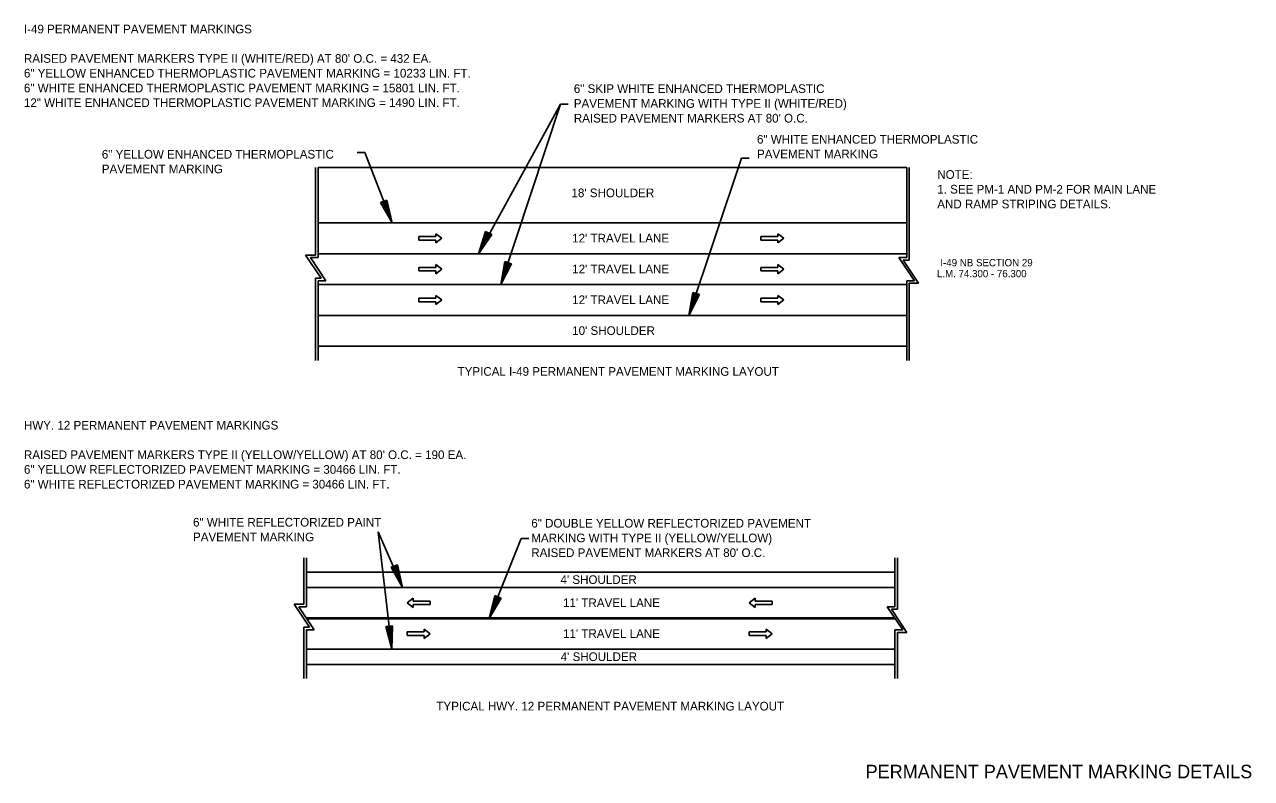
# Model space of a CAD drawing. Extents: x 2261938 to 2263136, y -3124572 to -3124216.
# Drawn here: x 2262297 to 2262456.3, y -3124313.5 to -3124215.6 of the extents above; entities that cross this region are included whole.
import ezdxf

# ---------------------------------------------------------------- set-up
doc = ezdxf.new("R2010")
doc.units = 0
for name, color, linetype in [('Default', 7, 'Continuous'), ('DSN_DRFT_Common-Annotations', 7, 'Continuous'), ('R_Draft', 7, 'Continuous'), ('SHET_Border-Text', 7, 'Continuous')]:
    doc.layers.add(name, color=color, linetype=linetype)

msp = doc.modelspace()

# ---------------------------------------------------------------- linework, layer by layer
at = {"layer": 'Default'}
for p, q in [((2262366.59, -3124225.98), (2262355.93, -3124245.39)), ((2262366.59, -3124225.98), (2262358.85, -3124249.39)), ((2262367.59, -3124225.98), (2262366.59, -3124225.98)), ((2262340.19, -3124232.23), (2262341.19, -3124232.23)), ((2262341.19, -3124232.23), (2262344.71, -3124241.39)), ((2262390.08, -3124233), (2262383.23, -3124253.39)), ((2262391.08, -3124233), (2262390.08, -3124233)), ((2262334.79, -3124234.19), (2262334.79, -3124245.56)), ((2262335.13, -3124234.19), (2262411.52, -3124234.19)), ((2262335.13, -3124234.19), (2262335.13, -3124245.89)), ((2262411.52, -3124234.19), (2262411.52, -3124245.89)), ((2262411.85, -3124234.19), (2262411.85, -3124246.23)), ((2262344.05, -3124238.43), (2262343.21, -3124238.75)), ((2262343.21, -3124238.75), (2262344.71, -3124241.39)), ((2262343.28, -3124238.73), (2262344.53, -3124240.93)), ((2262343.35, -3124238.7), (2262344.34, -3124240.44)), ((2262343.42, -3124238.67), (2262344.16, -3124239.98)), ((2262343.5, -3124238.64), (2262343.98, -3124239.5)), ((2262343.57, -3124238.62), (2262343.8, -3124239.03)), ((2262343.7, -3124238.57), (2262343.8, -3124239.03)), ((2262343.77, -3124238.54), (2262343.98, -3124239.5)), ((2262343.84, -3124238.51), (2262344.16, -3124239.98)), ((2262343.91, -3124238.49), (2262344.34, -3124240.44)), ((2262343.98, -3124238.46), (2262344.53, -3124240.93)), ((2262344.05, -3124238.43), (2262344.71, -3124241.39)), ((2262350.38, -3124242.79), (2262350.38, -3124243.17)), ((2262350.38, -3124242.79), (2262351.16, -3124243.39)), ((2262356.86, -3124242.51), (2262355.93, -3124245.39)), ((2262357.67, -3124242.91), (2262355.93, -3124245.39)), ((2262356.93, -3124242.54), (2262356.15, -3124244.94)), ((2262357.6, -3124242.87), (2262356.15, -3124244.94)), ((2262357, -3124242.57), (2262356.38, -3124244.48)), ((2262357.53, -3124242.84), (2262356.38, -3124244.48)), ((2262357.06, -3124242.61), (2262356.6, -3124244.03)), ((2262357.46, -3124242.81), (2262356.6, -3124244.03)), ((2262357.13, -3124242.64), (2262356.83, -3124243.58)), ((2262357.39, -3124242.77), (2262356.83, -3124243.58)), ((2262357.67, -3124242.91), (2262356.86, -3124242.51)), ((2262357.2, -3124242.67), (2262357.05, -3124243.13)), ((2262357.33, -3124242.74), (2262357.05, -3124243.13)), ((2262394.8, -3124242.79), (2262394.8, -3124243.17)), ((2262394.8, -3124242.79), (2262395.58, -3124243.39)), ((2262350.38, -3124243.17), (2262348.18, -3124243.17)), ((2262348.18, -3124243.17), (2262348.18, -3124243.62)), ((2262350.38, -3124243.62), (2262348.18, -3124243.62)), ((2262351.16, -3124243.39), (2262350.38, -3124243.99)), ((2262350.38, -3124243.62), (2262350.38, -3124243.99)), ((2262394.8, -3124243.17), (2262392.59, -3124243.17)), ((2262392.59, -3124243.17), (2262392.59, -3124243.62)), ((2262394.8, -3124243.62), (2262392.59, -3124243.62)), ((2262395.58, -3124243.39), (2262394.8, -3124243.99)), ((2262394.8, -3124243.62), (2262394.8, -3124243.99)), ((2262335.5, -3124248.56), (2262333.5, -3124245.56)), ((2262334.79, -3124245.56), (2262333.5, -3124245.56)), ((2262335.13, -3124245.89), (2262334.13, -3124245.89)), ((2262336.13, -3124248.89), (2262334.13, -3124245.89)), ((2262335.13, -3124245.39), (2262411.52, -3124245.39)), ((2262411.52, -3124245.89), (2262410.52, -3124245.89)), ((2262412.52, -3124248.89), (2262410.52, -3124245.89)), ((2262350.38, -3124247.17), (2262348.18, -3124247.17)), ((2262348.18, -3124247.17), (2262348.18, -3124247.62)), ((2262350.38, -3124247.62), (2262348.18, -3124247.62)), ((2262350.38, -3124246.79), (2262350.38, -3124247.17)), ((2262350.38, -3124246.79), (2262351.16, -3124247.39)), ((2262351.16, -3124247.39), (2262350.38, -3124247.99)), ((2262350.38, -3124247.62), (2262350.38, -3124247.99)), ((2262359.36, -3124246.4), (2262358.85, -3124249.39)), ((2262360.22, -3124246.69), (2262358.85, -3124249.39)), ((2262359.44, -3124246.43), (2262359.01, -3124248.92)), ((2262360.15, -3124246.66), (2262359.01, -3124248.92)), ((2262359.51, -3124246.45), (2262359.17, -3124248.43)), ((2262360.08, -3124246.64), (2262359.17, -3124248.43)), ((2262359.58, -3124246.47), (2262359.33, -3124247.95)), ((2262360, -3124246.61), (2262359.33, -3124247.95)), ((2262360.22, -3124246.69), (2262359.36, -3124246.4)), ((2262359.65, -3124246.5), (2262359.49, -3124247.47)), ((2262359.93, -3124246.59), (2262359.49, -3124247.47)), ((2262359.73, -3124246.52), (2262359.64, -3124246.99)), ((2262359.86, -3124246.57), (2262359.64, -3124246.99)), ((2262394.8, -3124247.17), (2262392.59, -3124247.17)), ((2262392.59, -3124247.17), (2262392.59, -3124247.62)), ((2262394.8, -3124247.62), (2262392.59, -3124247.62)), ((2262394.8, -3124246.79), (2262394.8, -3124247.17)), ((2262394.8, -3124246.79), (2262395.58, -3124247.39)), ((2262395.58, -3124247.39), (2262394.8, -3124247.99)), ((2262394.8, -3124247.62), (2262394.8, -3124247.99)), ((2262413.07, -3124249.23), (2262411.07, -3124246.23)), ((2262411.85, -3124246.23), (2262411.07, -3124246.23)), ((2262334.79, -3124248.56), (2262335.5, -3124248.56)), ((2262334.79, -3124259.23), (2262334.79, -3124248.56)), ((2262335.13, -3124259.23), (2262335.13, -3124248.89)), ((2262335.13, -3124248.89), (2262336.13, -3124248.89)), ((2262411.52, -3124259.23), (2262411.52, -3124248.89)), ((2262411.52, -3124248.89), (2262412.52, -3124248.89)), ((2262411.85, -3124259.23), (2262411.85, -3124249.23)), ((2262411.85, -3124249.23), (2262413.07, -3124249.23)), ((2262335.13, -3124249.39), (2262411.52, -3124249.39)), ((2262350.38, -3124250.79), (2262350.38, -3124251.17)), ((2262350.38, -3124250.79), (2262351.16, -3124251.39)), ((2262383.76, -3124250.41), (2262383.23, -3124253.39)), ((2262384.61, -3124250.69), (2262383.23, -3124253.39)), ((2262383.83, -3124250.43), (2262383.39, -3124252.92)), ((2262384.54, -3124250.67), (2262383.39, -3124252.92)), ((2262383.9, -3124250.45), (2262383.55, -3124252.43)), ((2262384.47, -3124250.64), (2262383.55, -3124252.43)), ((2262383.97, -3124250.48), (2262383.71, -3124251.96)), ((2262384.4, -3124250.62), (2262383.71, -3124251.96)), ((2262384.61, -3124250.69), (2262383.76, -3124250.41)), ((2262384.05, -3124250.5), (2262383.88, -3124251.47)), ((2262384.32, -3124250.6), (2262383.88, -3124251.47)), ((2262384.12, -3124250.53), (2262384.04, -3124251)), ((2262384.25, -3124250.57), (2262384.04, -3124251)), ((2262394.8, -3124250.79), (2262394.8, -3124251.17)), ((2262394.8, -3124250.79), (2262395.58, -3124251.39)), ((2262350.38, -3124251.17), (2262348.18, -3124251.17)), ((2262348.18, -3124251.17), (2262348.18, -3124251.62)), ((2262350.38, -3124251.62), (2262348.18, -3124251.62)), ((2262351.16, -3124251.39), (2262350.38, -3124251.99)), ((2262350.38, -3124251.62), (2262350.38, -3124251.99)), ((2262394.8, -3124251.17), (2262392.59, -3124251.17)), ((2262392.59, -3124251.17), (2262392.59, -3124251.62)), ((2262394.8, -3124251.62), (2262392.59, -3124251.62)), ((2262395.58, -3124251.39), (2262394.8, -3124251.99)), ((2262394.8, -3124251.62), (2262394.8, -3124251.99)), ((2262335.13, -3124253.39), (2262411.52, -3124253.39)), ((2262335.13, -3124257.39), (2262411.52, -3124257.39)), ((2262342.92, -3124281.48), (2262346.09, -3124288.71)), ((2262342.92, -3124281.48), (2262344.69, -3124296.71)), ((2262361.49, -3124282.35), (2262357.34, -3124292.71)), ((2262362.49, -3124282.35), (2262361.49, -3124282.35)), ((2262333.28, -3124284.87), (2262333.28, -3124290.87)), ((2262333.61, -3124284.87), (2262333.61, -3124291.21)), ((2262345.44, -3124285.75), (2262344.6, -3124286.07)), ((2262344.88, -3124285.96), (2262345.37, -3124286.82)), ((2262344.95, -3124285.93), (2262345.19, -3124286.35)), ((2262345.08, -3124285.88), (2262345.19, -3124286.35)), ((2262345.15, -3124285.85), (2262345.37, -3124286.82)), ((2262345.23, -3124285.83), (2262345.55, -3124287.29)), ((2262345.3, -3124285.8), (2262345.73, -3124287.76)), ((2262345.37, -3124285.77), (2262345.91, -3124288.24)), ((2262345.44, -3124285.75), (2262346.09, -3124288.71)), ((2262410, -3124284.87), (2262410, -3124291.21)), ((2262410.34, -3124284.87), (2262410.34, -3124291.54)), ((2262333.61, -3124286.71), (2262410, -3124286.71)), ((2262344.6, -3124286.07), (2262346.09, -3124288.71)), ((2262344.67, -3124286.04), (2262345.91, -3124288.24)), ((2262344.74, -3124286.01), (2262345.73, -3124287.76)), ((2262344.81, -3124285.99), (2262345.55, -3124287.29)), ((2262333.61, -3124288.71), (2262410, -3124288.71)), ((2262346.66, -3124290.71), (2262347.44, -3124290.11)), ((2262347.44, -3124291.31), (2262346.66, -3124290.71)), ((2262347.44, -3124290.48), (2262347.44, -3124290.11)), ((2262347.44, -3124290.48), (2262349.65, -3124290.48)), ((2262349.65, -3124290.93), (2262349.65, -3124290.48)), ((2262358.04, -3124289.76), (2262357.34, -3124292.71)), ((2262358.87, -3124290.09), (2262357.34, -3124292.71)), ((2262358.11, -3124289.78), (2262357.52, -3124292.24)), ((2262358.8, -3124290.06), (2262357.52, -3124292.24)), ((2262358.18, -3124289.81), (2262357.71, -3124291.76)), ((2262358.73, -3124290.03), (2262357.71, -3124291.76)), ((2262358.25, -3124289.84), (2262357.9, -3124291.3)), ((2262358.66, -3124290.01), (2262357.9, -3124291.3)), ((2262358.87, -3124290.09), (2262358.04, -3124289.76)), ((2262358.32, -3124289.87), (2262358.09, -3124290.83)), ((2262358.59, -3124289.98), (2262358.09, -3124290.83)), ((2262358.39, -3124289.9), (2262358.28, -3124290.36)), ((2262358.52, -3124289.95), (2262358.28, -3124290.36)), ((2262391.08, -3124290.71), (2262391.85, -3124290.11)), ((2262391.85, -3124291.31), (2262391.08, -3124290.71)), ((2262391.85, -3124290.48), (2262391.85, -3124290.11)), ((2262391.85, -3124290.48), (2262394.06, -3124290.48)), ((2262394.06, -3124290.93), (2262394.06, -3124290.48)), ((2262333.99, -3124293.87), (2262331.99, -3124290.87)), ((2262333.28, -3124290.87), (2262331.99, -3124290.87)), ((2262333.61, -3124291.21), (2262332.61, -3124291.21)), ((2262334.61, -3124294.21), (2262332.61, -3124291.21)), ((2262347.44, -3124290.93), (2262349.65, -3124290.93)), ((2262347.44, -3124291.31), (2262347.44, -3124290.93)), ((2262391.85, -3124290.93), (2262394.06, -3124290.93)), ((2262391.85, -3124291.31), (2262391.85, -3124290.93)), ((2262410, -3124291.21), (2262409, -3124291.21)), ((2262411, -3124294.21), (2262409, -3124291.21)), ((2262411.56, -3124294.54), (2262409.56, -3124291.54)), ((2262410.34, -3124291.54), (2262409.56, -3124291.54)), ((2262333.28, -3124293.87), (2262333.99, -3124293.87)), ((2262333.28, -3124300.54), (2262333.28, -3124293.87)), ((2262333.58, -3124292.66), (2262409.97, -3124292.66)), ((2262344.79, -3124293.68), (2262343.9, -3124293.78)), ((2262343.9, -3124293.78), (2262344.69, -3124296.71)), ((2262343.97, -3124293.77), (2262344.63, -3124296.21)), ((2262344.05, -3124293.76), (2262344.57, -3124295.7)), ((2262344.12, -3124293.75), (2262344.51, -3124295.2)), ((2262344.2, -3124293.74), (2262344.46, -3124294.7)), ((2262344.27, -3124293.74), (2262344.4, -3124294.2)), ((2262344.41, -3124293.72), (2262344.4, -3124294.2)), ((2262344.49, -3124293.71), (2262344.46, -3124294.7)), ((2262344.56, -3124293.7), (2262344.51, -3124295.2)), ((2262344.64, -3124293.69), (2262344.57, -3124295.7)), ((2262344.72, -3124293.68), (2262344.63, -3124296.21)), ((2262344.79, -3124293.68), (2262344.69, -3124296.71)), ((2262333.61, -3124300.54), (2262333.61, -3124294.21)), ((2262333.61, -3124294.21), (2262334.61, -3124294.21)), ((2262348.87, -3124294.48), (2262346.66, -3124294.48)), ((2262346.66, -3124294.48), (2262346.66, -3124294.93)), ((2262348.87, -3124294.93), (2262346.66, -3124294.93)), ((2262348.87, -3124294.11), (2262348.87, -3124294.48)), ((2262348.87, -3124294.11), (2262349.65, -3124294.71)), ((2262349.65, -3124294.71), (2262348.87, -3124295.31)), ((2262348.87, -3124294.93), (2262348.87, -3124295.31)), ((2262393.28, -3124294.48), (2262391.08, -3124294.48)), ((2262391.08, -3124294.48), (2262391.08, -3124294.93)), ((2262393.28, -3124294.93), (2262391.08, -3124294.93)), ((2262393.28, -3124294.11), (2262393.28, -3124294.48)), ((2262393.28, -3124294.11), (2262394.06, -3124294.71)), ((2262394.06, -3124294.71), (2262393.28, -3124295.31)), ((2262393.28, -3124294.93), (2262393.28, -3124295.31)), ((2262410, -3124300.54), (2262410, -3124294.21)), ((2262410, -3124294.21), (2262411, -3124294.21)), ((2262410.34, -3124300.54), (2262410.34, -3124294.54)), ((2262410.34, -3124294.54), (2262411.56, -3124294.54)), ((2262333.61, -3124296.71), (2262410, -3124296.71)), ((2262333.61, -3124298.71), (2262410, -3124298.71))]:
    msp.add_line(p, q, dxfattribs=at)
at = {"layer": 'R_Draft'}
for p, q in [((2262335.13, -3124241.39), (2262411.52, -3124241.39)), ((2262333.65, -3124292.76), (2262410.04, -3124292.76))]:
    msp.add_line(p, q, dxfattribs=at)

# ---------------------------------------------------------------- texts
at = {"layer": 'Default'}
for s, p in [('I-49 PERMANENT PAVEMENT MARKINGS', (2262296.93, -3124216.79)), ("RAISED PAVEMENT MARKERS TYPE II (WHITE/RED) AT 80' O.C. = 432 EA.", (2262296.93, -3124220.61)), ('6" YELLOW ENHANCED THERMOPLASTIC PAVEMENT MARKING = 10233 LIN. FT.', (2262296.93, -3124222.52)), ('6" WHITE ENHANCED THERMOPLASTIC PAVEMENT MARKING = 15801 LIN. FT.', (2262296.93, -3124224.44)), ('6" SKIP WHITE ENHANCED THERMOPLASTIC', (2262368.31, -3124224.53)), ('12" WHITE ENHANCED THERMOPLASTIC PAVEMENT MARKING = 1490 LIN. FT.', (2262296.93, -3124226.35)), ('PAVEMENT MARKING WITH TYPE II (WHITE/RED)', (2262368.31, -3124226.45)), ("RAISED PAVEMENT MARKERS AT 80' O.C.", (2262368.31, -3124228.36)), ('6" WHITE ENHANCED THERMOPLASTIC', (2262392.09, -3124231.1)), ('6" YELLOW ENHANCED THERMOPLASTIC', (2262307.04, -3124233.04)), ('PAVEMENT MARKING', (2262392.09, -3124233.01)), ('PAVEMENT MARKING', (2262307.04, -3124234.95)), ('NOTE:', (2262415.49, -3124235.67)), ('1. SEE PM-1 AND PM-2 FOR MAIN LANE', (2262415.49, -3124237.58)), ("18' SHOULDER", (2262368.01, -3124238.05)), ('AND RAMP STRIPING DETAILS.', (2262415.49, -3124239.5)), ("12' TRAVEL LANE", (2262368.1, -3124243.93)), ("12' TRAVEL LANE", (2262368.1, -3124247.93)), ("12' TRAVEL LANE", (2262368.1, -3124251.93)), ("10' SHOULDER", (2262368.1, -3124255.93)), ('TYPICAL I-49 PERMANENT PAVEMENT MARKING LAYOUT', (2262353.22, -3124261.23)), ('HWY. 12 PERMANENT PAVEMENT MARKINGS', (2262296.93, -3124268.21)), ("RAISED PAVEMENT MARKERS TYPE II (YELLOW/YELLOW) AT 80' O.C. = 190 EA.", (2262296.93, -3124272.04)), ('6" YELLOW REFLECTORIZED PAVEMENT MARKING = 30466 LIN. FT.', (2262296.93, -3124273.95)), ('6" WHITE REFLECTORIZED PAVEMENT MARKING = 30466 LIN. FT.', (2262296.93, -3124275.86)), ('6" WHITE REFLECTORIZED PAINT', (2262318.88, -3124280.8)), ('6" DOUBLE YELLOW REFLECTORIZED PAVEMENT', (2262362.79, -3124280.93)), ('PAVEMENT MARKING', (2262318.88, -3124282.71)), ('MARKING WITH TYPE II (YELLOW/YELLOW)', (2262362.79, -3124282.84)), ("RAISED PAVEMENT MARKERS AT 80' O.C.", (2262362.79, -3124284.75)), ("4' SHOULDER", (2262366.58, -3124288.25)), ("11' TRAVEL LANE", (2262366.91, -3124291.25)), ("11' TRAVEL LANE", (2262366.91, -3124295.25)), ("4' SHOULDER", (2262366.61, -3124298.25)), ('TYPICAL HWY. 12 PERMANENT PAVEMENT MARKING LAYOUT', (2262350.47, -3124304.67))]:
    msp.add_text(s, height=1.125, dxfattribs=at).set_placement(p)
at = {"layer": 'DSN_DRFT_Common-Annotations'}
for s, p in [('I-49 NB SECTION 29', (2262415.89, -3124247.02)), ('L.M. 74.300 - 76.300', (2262415.45, -3124248.44))]:
    msp.add_text(s, height=0.943, dxfattribs=at).set_placement(p)
at = {"layer": 'SHET_Border-Text'}
msp.add_text('PERMANENT PAVEMENT MARKING DETAILS', height=1.75, dxfattribs=at).set_placement((2262406.19, -3124313.47))

doc.saveas('drawing.dxf')
